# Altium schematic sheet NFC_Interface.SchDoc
size A4
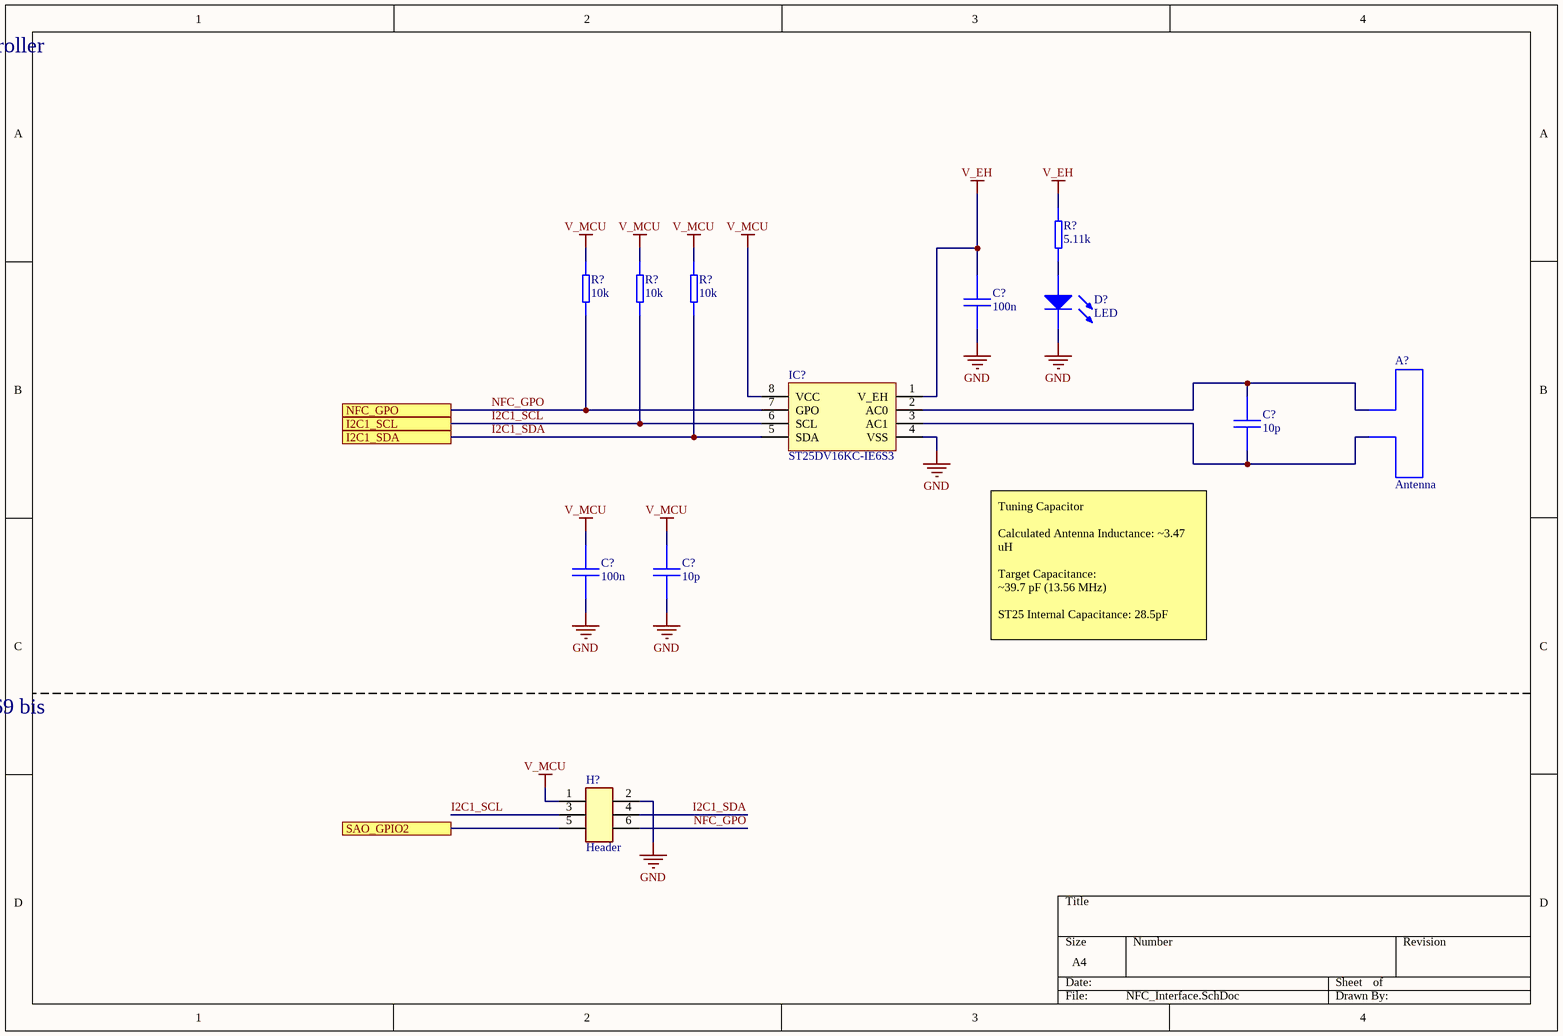
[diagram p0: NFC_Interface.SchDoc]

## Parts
(Parts that share a designator on the sheet are numbered #1, #2 ... from top to bottom, then left to right.)
A?  Antenna  [NFC Antenna 45 x 37]  (net tie, no BOM)
C?#1  100n  [CAP0805]
C?#2  10p  [CAP0402]
C?#3  100n  [CAP0805]
C?#4  10p  [CAP0402]
D?  LED  [LEDM2012X80N]
H?  Header  [HEADER_2X3]
IC?  ST25DV16KC-IE6S3  [SOIC8]
R?#1  5.11k  [RESC0805]
R?#2  10k  [RESC0805]
R?#3  10k  [RESC0805]
R?#4  10k  [RESC0805]

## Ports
I2C1_SCL, I2C1_SDA, NFC_GPO, SAO_GPIO2

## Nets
GND: C?#1.2 C?#3.2 C?#4.2 D?.1(K) H?.2 IC?.4(VSS)
V_EH: C?#1.1 IC?.1(V_EH) R?#1.1
V_MCU: C?#3.1 C?#4.1 H?.1 IC?.8(VCC) R?#2.1 R?#3.1 R?#4.1
I2C1_SCL: H?.3 IC?.6(SCL) R?#3.2 ; port I2C1_SCL
I2C1_SDA: H?.4 IC?.5(SDA) R?#4.2 ; port I2C1_SDA
NFC_GPO: H?.6 IC?.7(GPO) R?#2.2 ; port NFC_GPO
SAO_GPIO2: H?.5 ; port SAO_GPIO2
NetA?_1: A?.1 C?#2.1 IC?.2(AC0)
NetA?_2: A?.2 C?#2.2 IC?.3(AC1)
NetD?_2: D?.2(A) R?#1.2

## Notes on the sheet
- NFC Controller
- Tuning Capacitor
  Calculated Antenna Inductance: ~3.47 uH
  Target Capacitance:
  ~39.7 pF (13.56 MHz)
  ST25 Internal Capacitance: 28.5pF
- SAO V1.69 bis

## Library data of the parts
A? = Antenna - Dual Ended 2: Antenna - Dual Ended
C?#1-C?#4 = Capacitor - Non Polarized: Non Polarized Capacitor
D? = LED: General Purpose LED
H? = 6-Pin Header (3x2): 6-Pin 2 Row Header
IC? = ST25DV16KC-IE6S3: Integrated Circuit; Manufacturer_Name: STMicroelectronics
R?#1-R?#4 = Resistor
